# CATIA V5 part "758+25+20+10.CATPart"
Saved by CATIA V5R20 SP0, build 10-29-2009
Part number: 758+25+20+10
Revision: TUTTO
Definition: NON CONOSCIUTO
Nomenclature: 758+25+20+10
Source: Unknown
Bounding box of the stored display mesh (mm): x -12.31 to 12.31, y 0 to 20, z -12.5 to 12.5
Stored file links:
  C:\Users\Utente\Desktop\IO LAVORO\3D X SITO CF\X 3D SITO CF 27-09-2020\758\758+25+20+10.CATPart
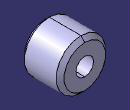
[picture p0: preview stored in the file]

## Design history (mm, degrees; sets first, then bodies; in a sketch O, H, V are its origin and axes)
Body1 "Importato1" (main body)
  Solid1: solid without history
